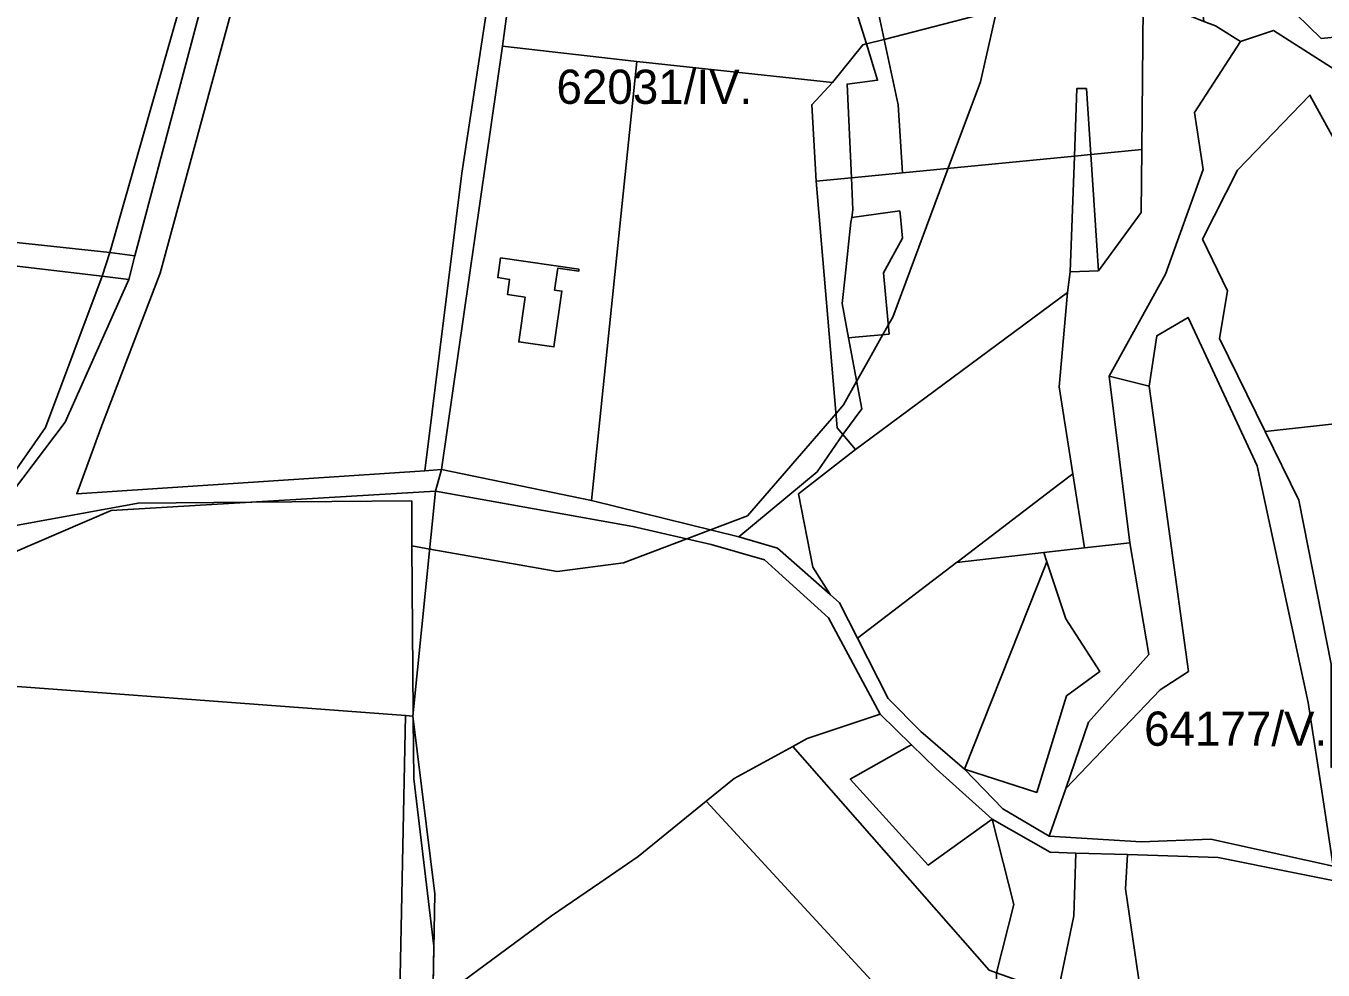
# Model space of a CAD drawing. Extents: x -502026 to -497664, y -1143484 to -1138019.
# Drawn here: x -499392.2 to -499088.9, y -1141619.2 to -1141398.4 of the extents above; entities that cross this region are included whole.
import ezdxf

# ---------------------------------------------------------------- set-up
doc = ezdxf.new("R2010")
doc.units = 0
for name, color, linetype in [('25', 7, 'Continuous'), ('37', 7, 'Continuous'), ('43', 7, 'Continuous'), ('55', 7, 'Continuous'), ('62', 7, 'Continuous'), ('7', 7, 'Continuous')]:
    doc.layers.add(name, color=color, linetype=linetype)

msp = doc.modelspace()

# ---------------------------------------------------------------- linework, layer by layer
at = {"layer": '25'}
for points in [[(-499168.6, -1141395.65), (-499191.5, -1141401.57), (-499192.88, -1141395.03), (-499171.72, -1141386.96)], [(-499124.43, -1141394.27), (-499130.95, -1141393.98), (-499131.23, -1141427.31), (-499143.18, -1141428.47), (-499144.19, -1141413.06), (-499146.45, -1141413.06), (-499147.01, -1141428.84), (-499187.22, -1141432.76), (-499188.25, -1141416.88), (-499191.5, -1141401.57), (-499168.6, -1141395.65), (-499149.98, -1141391.9), (-499140.52, -1141391.5)], [(-499143.18, -1141428.47), (-499147.01, -1141428.84), (-499146.45, -1141413.06), (-499144.19, -1141413.06)], [(-499147.98, -1141455.89), (-499148.62, -1141460.78), (-499198.18, -1141497.47), (-499201.16, -1141493.93), (-499196.74, -1141487.95), (-499199.86, -1141471.32), (-499198.31, -1141471.18), (-499190.37, -1141470.49), (-499191.62, -1141456.14), (-499187.19, -1141448.06), (-499187.71, -1141443.09), (-499187.86, -1141441.69), (-499199.1, -1141443.21), (-499198.8, -1141441.39), (-499199.15, -1141433.93), (-499187.22, -1141432.76), (-499147.01, -1141428.84)], [(-499141.39, -1141455.72), (-499147.98, -1141455.89), (-499147.01, -1141428.84), (-499143.18, -1141428.47)], [(-499141.39, -1141455.72), (-499143.18, -1141428.47), (-499131.23, -1141427.31), (-499131.36, -1141442.01)], [(-499147.37, -1141503.12), (-499150.86, -1141505.78), (-499174.46, -1141523.8), (-499174.57, -1141523.88), (-499197.76, -1141541.58), (-499201.98, -1141533.32), (-499204.16, -1141531.39), (-499208.15, -1141525.01), (-499211.51, -1141507.84), (-499198.18, -1141497.47), (-499148.62, -1141460.78), (-499150.56, -1141482.81)], [(-499198.18, -1141497.47), (-499211.51, -1141507.84), (-499208.15, -1141525.01), (-499204.16, -1141531.39), (-499216.44, -1141520.5), (-499225.49, -1141517.88), (-499207.15, -1141502.67), (-499201.16, -1141493.93)], [(-499144.65, -1141520.49), (-499154.18, -1141521.57), (-499174.57, -1141523.88), (-499174.46, -1141523.8), (-499150.86, -1141505.78), (-499147.37, -1141503.12)], [(-499153.46, -1141523.7), (-499172.75, -1141572.23), (-499182.94, -1141563.37), (-499190.53, -1141555.72), (-499197.76, -1141541.58), (-499174.57, -1141523.88), (-499154.18, -1141521.57)], [(-499172.75, -1141572.23), (-499153.46, -1141523.7), (-499148.99, -1141537.04), (-499141.08, -1141549.4), (-499148.85, -1141555.09), (-499155.83, -1141577.63)], [(-499185.07, -1141566.51), (-499186.03, -1141566.99), (-499199.43, -1141574.55), (-499181.24, -1141594.64), (-499166.23, -1141583.87), (-499161.16, -1141603.88), (-499165.22, -1141619.86), (-499166.97, -1141619.24), (-499212.87, -1141566.9), (-499209.49, -1141565.05), (-499192.44, -1141559.35)]]:
    msp.add_lwpolyline(points, close=True, dxfattribs=at)
at = {"layer": '37'}
for points in [[(-499074.21, -1141304.14), (-499073.8, -1141346.7), (-499082.76, -1141364.23), (-499070.12, -1141399.39), (-499089.26, -1141401.36), (-499098.14, -1141392.81), (-499102.44, -1141380.96), (-499099.88, -1141378.06), (-499104.41, -1141362.84), (-499108.71, -1141364.7), (-499121.02, -1141347.74), (-499117.07, -1141344.72), (-499126.59, -1141327.76), (-499132.13, -1141317.02), (-499122.41, -1141305.69), (-499099.42, -1141303.13)], [(-499269.39, -1141326.63), (-499273.88, -1141341.94), (-499283.15, -1141386.25), (-499290.24, -1141432.82), (-499298.96, -1141502.43), (-499380.34, -1141507.82), (-499374.68, -1141492.44), (-499360.85, -1141456.27), (-499330.87, -1141346.07), (-499318.37, -1141314.58), (-499265.69, -1141307)], [(-499192.88, -1141395.03), (-499191.5, -1141401.57), (-499195.61, -1141402.63), (-499205.3, -1141371.89), (-499199.51, -1141363.72)], [(-499187.22, -1141432.76), (-499199.15, -1141433.93), (-499200.18, -1141412.02), (-499193.03, -1141411.12), (-499195.61, -1141402.63), (-499191.5, -1141401.57), (-499188.25, -1141416.88)], [(-499249.31, -1141406.75), (-499259.96, -1141509.41), (-499295.03, -1141502.17), (-499280.77, -1141403.17)], [(-499053.7, -1141487.88), (-499102.4, -1141493.22), (-499113.08, -1141471.53), (-499111.22, -1141460.38), (-499117.03, -1141448.3), (-499108.88, -1141432.13), (-499091.92, -1141414.58), (-499060.45, -1141471.88)], [(-499281.2, -1141452.63), (-499281.88, -1141457.28), (-499279.12, -1141457.7), (-499279.61, -1141461.22), (-499275.47, -1141461.82), (-499276.95, -1141472.29), (-499268.73, -1141473.46), (-499266.87, -1141460.43), (-499268.6, -1141460.17), (-499267.86, -1141455.07), (-499262.92, -1141455.78), (-499262.92, -1141455.29)], [(-499088.85, -1141579.34), (-499086.47, -1141594.92), (-499115.1, -1141588.54), (-499131.4, -1141589.23), (-499152.88, -1141587.86), (-499149.04, -1141576.7), (-499126.95, -1141553.67), (-499120.33, -1141549.34), (-499129.56, -1141482.67), (-499127.76, -1141470.88), (-499120.4, -1141466.57), (-499104.25, -1141501.27), (-499092.34, -1141556.64)], [(-499086.96, -1141571.81), (-499086.96, -1141547.65), (-499094.5, -1141509.29), (-499102.4, -1141493.22), (-499053.7, -1141487.88), (-499049.08, -1141498.83), (-499033.4, -1141514.28), (-499030.26, -1141524.85), (-499065.13, -1141547.8), (-499063.74, -1141563.83)], [(-499192.44, -1141559.35), (-499209.49, -1141565.05), (-499212.87, -1141566.9), (-499226.55, -1141574.37), (-499233.14, -1141579.71), (-499249.04, -1141592.59), (-499258.04, -1141598.79), (-499269.28, -1141606.52), (-499297.09, -1141627.02), (-499296.62, -1141601.34), (-499301.71, -1141559.8), (-499296.43, -1141507.22), (-499250.27, -1141515.5), (-499232, -1141519.68), (-499219.48, -1141523.27), (-499204.5, -1141536.85)], [(-499165.22, -1141619.86), (-499164.88, -1141634.68), (-499172.56, -1141645.39), (-499233.14, -1141579.71), (-499226.55, -1141574.37), (-499212.87, -1141566.9), (-499166.97, -1141619.24)], [(-499134.62, -1141592.19), (-499135.02, -1141600.22), (-499130.29, -1141632.61), (-499119.22, -1141664.12), (-499137.34, -1141664.25), (-499139.87, -1141664.27), (-499138.68, -1141660.18), (-499141.16, -1141638.42), (-499146.44, -1141630.23), (-499150.99, -1141624.87), (-499147.17, -1141606.51), (-499146.64, -1141591.81)], [(-498997.4, -1141647.48), (-499015.11, -1141653.67), (-499036.81, -1141671.03), (-499119.22, -1141664.12), (-499130.29, -1141632.61), (-499135.02, -1141600.22), (-499134.62, -1141592.19), (-499113.37, -1141592.87), (-499078.04, -1141599.95), (-499054.3, -1141597.84), (-499042.32, -1141598.82), (-499019.94, -1141604.31), (-499001.68, -1141617)]]:
    msp.add_lwpolyline(points, close=True, dxfattribs=at)
for points in [[(-499078.93, -1141413.23), (-499100.43, -1141399.49), (-499108.19, -1141402.05), (-499114.02, -1141398.44), (-499116.7, -1141397.37), (-499119.5, -1141374.51), (-499146.97, -1141336.63), (-499142.12, -1141334.13), (-499151.83, -1141324.21), (-499137.85, -1141323.69), (-499132.13, -1141317.02), (-499126.59, -1141327.76), (-499117.07, -1141344.72), (-499121.02, -1141347.74), (-499108.71, -1141364.7), (-499104.41, -1141362.84), (-499099.88, -1141378.06), (-499102.44, -1141380.96), (-499098.14, -1141392.81), (-499089.26, -1141401.36), (-499070.12, -1141399.39)], [(-499088.85, -1141579.34), (-499092.34, -1141556.64), (-499104.25, -1141501.27), (-499120.4, -1141466.57), (-499127.76, -1141470.88), (-499129.56, -1141482.67), (-499138.85, -1141480.31), (-499125.67, -1141456.44), (-499116.93, -1141432.03), (-499118.88, -1141418.7), (-499108.19, -1141402.05), (-499100.43, -1141399.49), (-499078.93, -1141413.23)], [(-499060.45, -1141471.88), (-499091.92, -1141414.58), (-499108.88, -1141432.13), (-499117.03, -1141448.3), (-499111.22, -1141460.38), (-499113.08, -1141471.53), (-499102.4, -1141493.22), (-499094.5, -1141509.29), (-499086.96, -1141547.65)]]:
    msp.add_lwpolyline(points, dxfattribs=at)
at = {"layer": '43'}
for points in [[(-499124.43, -1141394.27), (-499116.7, -1141397.37), (-499114.02, -1141398.44), (-499108.19, -1141402.05), (-499118.88, -1141418.7), (-499116.93, -1141432.03), (-499125.67, -1141456.44), (-499138.85, -1141480.31), (-499134.01, -1141519.28), (-499144.65, -1141520.49), (-499147.37, -1141503.12), (-499150.56, -1141482.81), (-499148.62, -1141460.78), (-499147.98, -1141455.89), (-499141.39, -1141455.72), (-499131.36, -1141442.01), (-499131.23, -1141427.31), (-499130.95, -1141393.98)], [(-499301.71, -1141559.8), (-499303.45, -1141559.67), (-499444.4, -1141549.12), (-499430.69, -1141536.82), (-499372.26, -1141511.76), (-499296.43, -1141507.22)], [(-499149.04, -1141576.7), (-499152.88, -1141587.86), (-499163.77, -1141581.45), (-499172.75, -1141572.23), (-499155.83, -1141577.63), (-499148.85, -1141555.09), (-499141.08, -1141549.4), (-499148.99, -1141537.04), (-499153.46, -1141523.7), (-499154.18, -1141521.57), (-499144.65, -1141520.49), (-499134.01, -1141519.28), (-499129.57, -1141545.37), (-499143.71, -1141561.22)], [(-499301.71, -1141559.8), (-499296.62, -1141601.34), (-499297.09, -1141627.02), (-499300.45, -1141662.82), (-499305.58, -1141662.72), (-499303.45, -1141559.67)]]:
    msp.add_lwpolyline(points, close=True, dxfattribs=at)
msp.add_lwpolyline([(-499524.78, -1141628.65), (-499494.96, -1141585.04), (-499484.76, -1141575.72), (-499444.4, -1141549.12), (-499303.45, -1141559.67), (-499305.58, -1141662.72)], dxfattribs=at)
at = {"layer": '55'}
for points in [[(-499269.18, -1141341.79), (-499274.46, -1141363.41), (-499278.27, -1141384.51), (-499280.77, -1141403.17), (-499295.03, -1141502.17), (-499298.96, -1141502.43), (-499290.24, -1141432.82), (-499283.15, -1141386.25), (-499273.88, -1141341.94), (-499269.39, -1141326.63), (-499271.06, -1141341.62)], [(-499343.75, -1141365.68), (-499366.75, -1141452.15), (-499372.6, -1141451.4), (-499347.89, -1141364.59)], [(-499199.86, -1141471.32), (-499201.36, -1141463.35), (-499200.66, -1141456.93), (-499199.28, -1141444.31), (-499199.1, -1141443.21), (-499187.86, -1141441.69), (-499187.71, -1141443.09), (-499187.19, -1141448.06), (-499191.62, -1141456.14), (-499190.37, -1141470.49), (-499198.31, -1141471.18)], [(-499415.61, -1141446.79), (-499372.6, -1141451.4), (-499374.4, -1141456.95), (-499403.03, -1141453.57), (-499433.66, -1141449.95), (-499433.17, -1141444.87)], [(-499366.75, -1141452.15), (-499368.18, -1141457.7), (-499374.4, -1141456.95), (-499372.6, -1141451.4)], [(-499281.2, -1141452.63), (-499262.92, -1141455.29), (-499262.92, -1141455.78), (-499267.86, -1141455.07), (-499268.6, -1141460.17), (-499266.87, -1141460.43), (-499268.73, -1141473.46), (-499276.95, -1141472.29), (-499275.47, -1141461.82), (-499279.61, -1141461.22), (-499279.12, -1141457.7), (-499281.88, -1141457.28)], [(-499368.18, -1141457.7), (-499383.03, -1141491.07), (-499400.53, -1141514.08), (-499402.56, -1141513.62), (-499387.63, -1141492.31), (-499374.4, -1141456.95)], [(-499129.56, -1141482.67), (-499120.33, -1141549.34), (-499126.95, -1141553.67), (-499149.04, -1141576.7), (-499143.71, -1141561.22), (-499129.57, -1141545.37), (-499134.01, -1141519.28), (-499138.85, -1141480.31)], [(-499166.23, -1141583.87), (-499181.24, -1141594.64), (-499199.43, -1141574.55), (-499186.03, -1141566.99), (-499185.07, -1141566.51), (-499179.32, -1141572.09)], [(-499146.64, -1141591.81), (-499147.17, -1141606.51), (-499150.99, -1141624.87), (-499165.22, -1141619.86), (-499161.16, -1141603.88), (-499166.23, -1141583.87), (-499152.68, -1141591.62)]]:
    msp.add_lwpolyline(points, close=True, dxfattribs=at)
for points in [[(-499330.87, -1141346.07), (-499360.85, -1141456.27), (-499374.68, -1141492.44), (-499380.34, -1141507.82), (-499298.96, -1141502.43), (-499295.03, -1141502.17), (-499296.43, -1141507.22), (-499372.26, -1141511.76), (-499430.69, -1141536.82)], [(-499400.53, -1141514.08), (-499383.03, -1141491.07), (-499368.18, -1141457.7), (-499366.75, -1141452.15), (-499343.75, -1141365.68)], [(-499078.04, -1141599.95), (-499113.37, -1141592.87), (-499134.62, -1141592.19), (-499146.64, -1141591.81), (-499152.68, -1141591.62), (-499166.23, -1141583.87), (-499179.32, -1141572.09), (-499185.07, -1141566.51), (-499192.44, -1141559.35), (-499204.5, -1141536.85), (-499219.48, -1141523.27), (-499232, -1141519.68), (-499250.27, -1141515.5), (-499296.43, -1141507.22), (-499295.03, -1141502.17), (-499259.96, -1141509.41), (-499225.49, -1141517.88), (-499216.44, -1141520.5), (-499204.16, -1141531.39), (-499201.98, -1141533.32), (-499197.76, -1141541.58), (-499190.53, -1141555.72), (-499182.94, -1141563.37), (-499172.75, -1141572.23), (-499163.77, -1141581.45), (-499152.88, -1141587.86), (-499131.4, -1141589.23), (-499115.1, -1141588.54), (-499086.47, -1141594.92)]]:
    msp.add_lwpolyline(points, dxfattribs=at)
at = {"layer": '62'}
for points in [[(-499165.22, -1141394.97), (-499169, -1141411.5), (-499176.54, -1141431.72), (-499189.5, -1141466.5), (-499190.55, -1141468.38), (-499191.27, -1141469.66), (-499191.81, -1141470.61), (-499194.92, -1141476.17), (-499197.94, -1141481.55), (-499201, -1141487), (-499202.75, -1141489.02), (-499223.5, -1141513), (-499232.09, -1141516.26), (-499237.68, -1141518.38), (-499252.5, -1141524), (-499268, -1141526), (-499297.79, -1141520.74), (-499302, -1141520), (-499302, -1141509.5), (-499339.39, -1141509.79), (-499366, -1141510), (-499401.5, -1141516.5)], [(-499297, -1141622.33), (-499296.84, -1141613.61), (-499301.5, -1141574.5), (-499301.63, -1141560.46), (-499301.71, -1141559.8), (-499301.64, -1141559.11), (-499302, -1141520), (-499297.79, -1141520.74), (-499268, -1141526), (-499252.5, -1141524), (-499237.68, -1141518.38), (-499232.09, -1141516.26), (-499223.5, -1141513), (-499202.75, -1141489.02), (-499201, -1141487), (-499197.94, -1141481.55), (-499194.92, -1141476.17), (-499191.81, -1141470.61), (-499191.27, -1141469.66), (-499190.55, -1141468.38), (-499189.5, -1141466.5), (-499176.54, -1141431.72), (-499169, -1141411.5), (-499165.22, -1141394.97)], [(-499401.5, -1141516.5), (-499366, -1141510), (-499339.39, -1141509.79), (-499302, -1141509.5), (-499302, -1141520), (-499301.64, -1141559.11), (-499301.71, -1141559.8), (-499301.63, -1141560.46), (-499301.5, -1141574.5), (-499296.84, -1141613.61), (-499297, -1141622.33)]]:
    msp.add_lwpolyline(points, dxfattribs=at)
at = {"layer": '7'}
for points in [[(-499347.89, -1141364.59), (-499372.6, -1141451.4), (-499415.61, -1141446.79), (-499410.26, -1141396.29), (-499405.29, -1141349.34), (-499401.28, -1141335.7), (-499404.91, -1141337.15), (-499401.45, -1141320.25), (-499385.94, -1141313.48), (-499400.09, -1141350.4)], [(-499205.3, -1141371.89), (-499195.61, -1141402.63), (-499196.51, -1141402.82), (-499203.57, -1141411.65), (-499249.31, -1141406.75), (-499280.77, -1141403.17), (-499278.27, -1141384.51), (-499274.46, -1141363.41)], [(-499199.15, -1141433.93), (-499207.38, -1141434.73), (-499208.44, -1141416.84), (-499203.57, -1141411.65), (-499196.51, -1141402.82), (-499195.61, -1141402.63), (-499193.03, -1141411.12), (-499200.18, -1141412.02)], [(-499203.57, -1141411.65), (-499208.44, -1141416.84), (-499207.38, -1141434.73), (-499202.46, -1141492.38), (-499201.16, -1141493.93), (-499207.15, -1141502.67), (-499225.49, -1141517.88), (-499259.96, -1141509.41), (-499249.31, -1141406.75)], [(-499199.1, -1141443.21), (-499199.28, -1141444.31), (-499200.66, -1141456.93), (-499201.36, -1141463.35), (-499199.86, -1141471.32), (-499196.74, -1141487.95), (-499201.16, -1141493.93), (-499202.46, -1141492.38), (-499207.38, -1141434.73), (-499199.15, -1141433.93), (-499198.8, -1141441.39)], [(-499374.4, -1141456.95), (-499387.63, -1141492.31), (-499402.56, -1141513.62), (-499408.41, -1141514.53), (-499419.7, -1141516.22), (-499403.03, -1141453.57)], [(-499172.56, -1141645.39), (-499192.55, -1141664.42), (-499237.21, -1141663.71), (-499300.45, -1141662.82), (-499297.09, -1141627.02), (-499269.28, -1141606.52), (-499258.04, -1141598.79), (-499249.04, -1141592.59), (-499233.14, -1141579.71)]]:
    msp.add_lwpolyline(points, close=True, dxfattribs=at)

# ---------------------------------------------------------------- texts
at = {"layer": '62'}
for s, p in [('62031/IV.', (-499268.14, -1141416.65)), ('64177/V.', (-499130.7, -1141566.74))]:
    msp.add_text(s, height=8, dxfattribs=at).set_placement(p)

doc.saveas('drawing.dxf')
